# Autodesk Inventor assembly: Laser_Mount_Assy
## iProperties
Shininess: 64.0
Length Units: 11269
Angle Units: 11279
Time Units: 11290
Mass Units: 11283
Length Display Precision: 3
Angle Display Precision: 2
Compacted: True
Created: 2004-08
Part Number: Laser_Mount_Assy
Document SubType Name: Assembly
Designer: John Blackburn
Manufacturer: Standard
Standards Organization: Custom
Density: 0.0
Volumn: 0.0
Area: 0.0
PropertySet Name: Model Information
Control State: 0
Master: False
Checked Out: False
Author: John Blackburn
